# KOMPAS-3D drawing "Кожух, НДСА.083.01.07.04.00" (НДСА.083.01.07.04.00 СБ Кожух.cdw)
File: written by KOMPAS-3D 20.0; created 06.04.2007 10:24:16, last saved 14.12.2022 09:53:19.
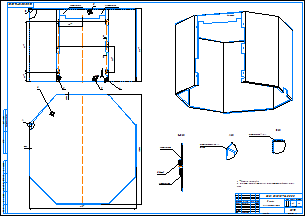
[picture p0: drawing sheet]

Sheet 1: A1, landscape

Document properties: Автор: Шубников; Организация: ЭСТО-Вакуум; Полное имя файла: C:\Users\cherbakova\Desktop\Виноград\Новая папка (4)\НДСА.083.01.07.04.00 СБ Кожух.cdw; PLM_CDWXDTO: <item xmlns="http://appius.ru/pdm" xmlns:xs="http://www.w3.org/2001/XMLSchema" xmlns:xsi="http://www.w3.org/2001/XMLSchema-instance" xsi:type="item">  <element xmlns:d2p1="http://v8.1c.ru/8.1/data/enterprise/current-config" xsi:type="d2p1:CatalogRef.aps_Элемен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; Масса: 8.48967; PDM_DOCXDTO: <item xmlns="http://appius.ru/pdm" xmlns:xs="http://www.w3.org/2001/XMLSchema" xmlns:xsi="http://www.w3.org/2001/XMLSchema-instance" xsi:type="item">  <element xmlns:d2p1="http://v8.1c.ru/8.1/data/enterprise/current-config" xsi:type="d2p1:CatalogRef.aps_Элемен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; PDM_ITEMXDTO: <item xmlns="http://appius.ru/pdm" xmlns:xs="http://www.w3.org/2001/XMLSchema" xmlns:xsi="http://www.w3.org/2001/XMLSchema-instance" xsi:type="item">  <element xmlns:d2p1="http://v8.1c.ru/8.1/data/enterprise/current-config" xsi:type="d2p1:CatalogRef.aps_Элемен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; PDM_DRAWINGXDTO: <item xmlns="http://appius.ru/pdm" xmlns:xs="http://www.w3.org/2001/XMLSchema" xmlns:xsi="http://www.w3.org/2001/XMLSchema-instance" xsi:type="item">  <element xmlns:d2p1="http://v8.1c.ru/8.1/data/enterprise/current-config" xsi:type="d2p1:CatalogRef.aps_Элемен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

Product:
- Part/product: Кожух  | designation НДСА.083.01.07.04.00
    Масса: 8.48967
    Раздел спецификации: Сборочные единицы
    additional columns: <item xmlns="http://appius.ru/pdm" xmlns:xs="http://www.w3.org/2001/XMLSchema" x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; <item xmlns="http://appius.ru/pdm" xmlns:xs="http://www.w3.org/2001/XMLSchema" x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; <item xmlns="http://appius.ru/pdm" xmlns:xs="http://www.w3.org/2001/XMLSchema" x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
    source file: НДСА.083.01.07.04.00 СБ Кожух.cdw
  - Component [detail]: Пластина  | designation НДСА.083.01.07.04.06  | qty 3  | pos. 5
      Материал: Лист$d4,0 ГОСТ 19903-74;10 ГОСТ 1050-88$ (density 7856 kg/m3)
      Масса: 0.00912487
      Раздел спецификации: Детали
      Форматы листов документа: A4
      additional columns: <item xmlns="http://appius.ru/pdm" xmlns:xs="http://www.w3.org/2001/XMLSchema" x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; <item xmlns="http://appius.ru/pdm" xmlns:xs="http://www.w3.org/2001/XMLSchema" x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; <item xmlns="http://appius.ru/pdm" xmlns:xs="http://www.w3.org/2001/XMLSchema" x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
      source file: НДСА.083.01.07.04.06 Пластина.cdw, НДСА.083.01.07.04.06 Пластина.m3d
  - Component [detail]: Пластина  | designation НДСА.083.01.07.04.06  | qty 3  | pos. 4
      Материал: Лист$d4,0 ГОСТ 19903-74;10 ГОСТ 1050-88$ (density 7856 kg/m3)
      Масса: 0.00912487
      Раздел спецификации: Детали
      Форматы листов документа: A4
      additional columns: <item xmlns="http://appius.ru/pdm" xmlns:xs="http://www.w3.org/2001/XMLSchema" x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; <item xmlns="http://appius.ru/pdm" xmlns:xs="http://www.w3.org/2001/XMLSchema" x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; <item xmlns="http://appius.ru/pdm" xmlns:xs="http://www.w3.org/2001/XMLSchema" x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
      source file: НДСА.083.01.07.04.06 Пластина.cdw, НДСА.083.01.07.04.06 Пластина.m3d
  - Component [detail]: Вставка  | designation НДСА.083.01.07.04.05  | pos. 7  | Масса: 0.112325; Раздел спецификации: Детали; Форматы листов документа: A4; additional columns: <item xmlns="http://appius.ru/pdm" xmlns:xs="http://www.w3.org/2001/XMLSchema" x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; <item xmlns="http://appius.ru/pdm" xmlns:xs="http://www.w3.org/2001/XMLSchema" x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; <item xmlns="http://appius.ru/pdm" xmlns:xs="http://www.w3.org/2001/XMLSchema" x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; source file: НДСА.083.01.07.04.05 Вставка.cdw, НДСА.083.01.07.04.05 Вставка.m3d
  - Component [detail]: Лист  | designation НДСА.083.01.07.04.02  | pos. 9
      Материал: Лист$d1 ГОСТ 19904-90;10 ГОСТ 16523-97$ (density 7856 kg/m3)
      Масса: 2.40243
      Раздел спецификации: Детали
      Форматы листов документа: A2
      additional columns: <item xmlns="http://appius.ru/pdm" xmlns:xs="http://www.w3.org/2001/XMLSchema" x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; <item xmlns="http://appius.ru/pdm" xmlns:xs="http://www.w3.org/2001/XMLSchema" x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; <item xmlns="http://appius.ru/pdm" xmlns:xs="http://www.w3.org/2001/XMLSchema" x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
      source file: НДСА.083.01.07.04.02 Лист.cdw, НДСА.083.01.07.04.02 Лист.m3d
  - Component [detail]: Лист  | designation НДСА.083.01.07.04.04  | pos. 11
      Материал: Лист$d1 ГОСТ 19904-90;10 ГОСТ 16523-97$ (density 7856 kg/m3)
      Масса: 1.68856
      Раздел спецификации: Детали
      Форматы листов документа: A2
      additional columns: <item xmlns="http://appius.ru/pdm" xmlns:xs="http://www.w3.org/2001/XMLSchema" x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; <item xmlns="http://appius.ru/pdm" xmlns:xs="http://www.w3.org/2001/XMLSchema" x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; <item xmlns="http://appius.ru/pdm" xmlns:xs="http://www.w3.org/2001/XMLSchema" x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; 0;Material:VDE12371B5FDD453AAD3A0896F0FE5778;Sortament:VBE6DDF6ADAD111D699300000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
      source file: НДСА.083.01.07.04.04 Лист.cdw, НДСА.083.01.07.04.04 Лист.m3d
  - Component [detail]: Лист  | designation НДСА.083.01.07.04.03  | pos. 3
      Материал: Лист$d1 ГОСТ 19904-90;10 ГОСТ 16523-97$ (density 7856 kg/m3)
      Масса: 1.72156
      Раздел спецификации: Детали
      Форматы листов документа: A2
      additional columns: <item xmlns="http://appius.ru/pdm" xmlns:xs="http://www.w3.org/2001/XMLSchema" x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; <item xmlns="http://appius.ru/pdm" xmlns:xs="http://www.w3.org/2001/XMLSchema" x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; <item xmlns="http://appius.ru/pdm" xmlns:xs="http://www.w3.org/2001/XMLSchema" x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; 0;Material:VDE12371B5FDD453AAD3A0896F0FE5778;Sortament:VBE6DDF6ADAD111D699300000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
      source file: НДСА.083.01.07.04.03 Лист.cdw, НДСА.083.01.07.04.03 Лист.m3d
  - Component [detail]: Лист  | designation НДСА.083.01.07.04.01  | pos. 6
      Материал: Лист$d1 ГОСТ 19904-90;10 ГОСТ 16523-97$ (density 7856 kg/m3)
      Масса: 2.51004
      Раздел спецификации: Детали
      Форматы листов документа: A2
      additional columns: <item xmlns="http://appius.ru/pdm" xmlns:xs="http://www.w3.org/2001/XMLSchema" x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; <item xmlns="http://appius.ru/pdm" xmlns:xs="http://www.w3.org/2001/XMLSchema" x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; <item xmlns="http://appius.ru/pdm" xmlns:xs="http://www.w3.org/2001/XMLSchema" x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; 0;Material:VDE12371B5FDD453AAD3A0896F0FE5778;Sortament:VBE6DDF6ADAD111D699300000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
      source file: НДСА.083.01.07.04.01 Лист.cdw, НДСА.083.01.07.04.01 Лист.m3d

Title block, sheet 1: Наименование: Кожух / Сборочный чертеж; Масса: 8,49; scale: 1:2; Количество листов документа: 1; organisation: ЭСТО; Форматы листов документа: A1; stored path: E:\WorkPDM\Шубников А.В\e42bffde-a7e8-49fc-b6c8-9b933a29f36d\УКРД.787.06.02.00.00 СБ Кожух.cdw; Разработал: Щербакова; Проверил: Горностаев; Утвердил: Белецкий; Разработал, date: 14.12.2022

Views: Проекционный вид 8, Местный разрез 1, Выносной элемент 13, Разрез Г-Г, Выносной элемент Б, Выносной элемент, Разрез В-В
Referenced files in C:\Users\reznika\Desktop\Конвертация\Крышка камеры\Новая крышка\: НДСА.015.01.06.03.01 Лист.m3d, НДСА.015.01.06.03.03 Лист.m3d, НДСА.015.01.06.03.05 Пластина.m3d
Referenced files in C:\Users\cherbakova\Desktop\Виноград\Новая папка (4)\: НДСА.083.01.07.04.00 Кожух.a3d, НДСА.083.01.07.04.06 Пластина.m3d, НДСА.083.01.07.04.04 Лист.m3d, НДСА.083.01.07.04.01 Лист.m3d, НДСА.083.01.07.04.06 Пластина.cdw, НДСА.083.01.07.04.03 Лист.m3d, НДСА.083.01.07.04.03 Лист.cdw, НДСА.083.01.07.04.01 Лист.cdw, НДСА.083.01.07.04.05 Вставка.m3d, НДСА.083.01.07.04.05 Вставка.cdw, НДСА.083.01.07.04.02 Лист.m3d, НДСА.083.01.07.04.02 Лист.cdw, НДСА.083.01.07.04.04 Лист.cdw
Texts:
  НДСА.083.01.07.04.00
  ГОСТ14771-76-Н1- -
  ГОСТ14771-76-Т1
  НДСА.083.01.07.04.06
  Пластина
  НДСА.083.01.07.04.03
  Лист
  НДСА.083.01.07.04.01
  НДСА.083.01.07.04.05
  Вставка
  НДСА.083.01.07.04.02
  НДСА.083.01.07.04.04
  УКРД.787.06.02.00.00
  НДСА.083.01.07.04.01 Лист
  НДСА.083.01.07.04.03 Лист
  НДСА.083.01.07.04.04 Лист
  НДСА.083.01.07.04.02  Лист
  НДСА.083.01.07.04.06 Пластина
  НДСА.083.01.07.04.05 Вставка
  НДСА.083.01.07.04.00 Кожух
Dimensions and other numbers on the sheet: 610±0,5; 3±0,5; 592; 2; 6(6шт.); 5; 1; 4; 6; 7; 9; 11; 1:2; 8,49; 14.12.2022

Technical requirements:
  * Размеры для справок.
  Покрытие эмаль светло-серая, мелкостуктурированная, номер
